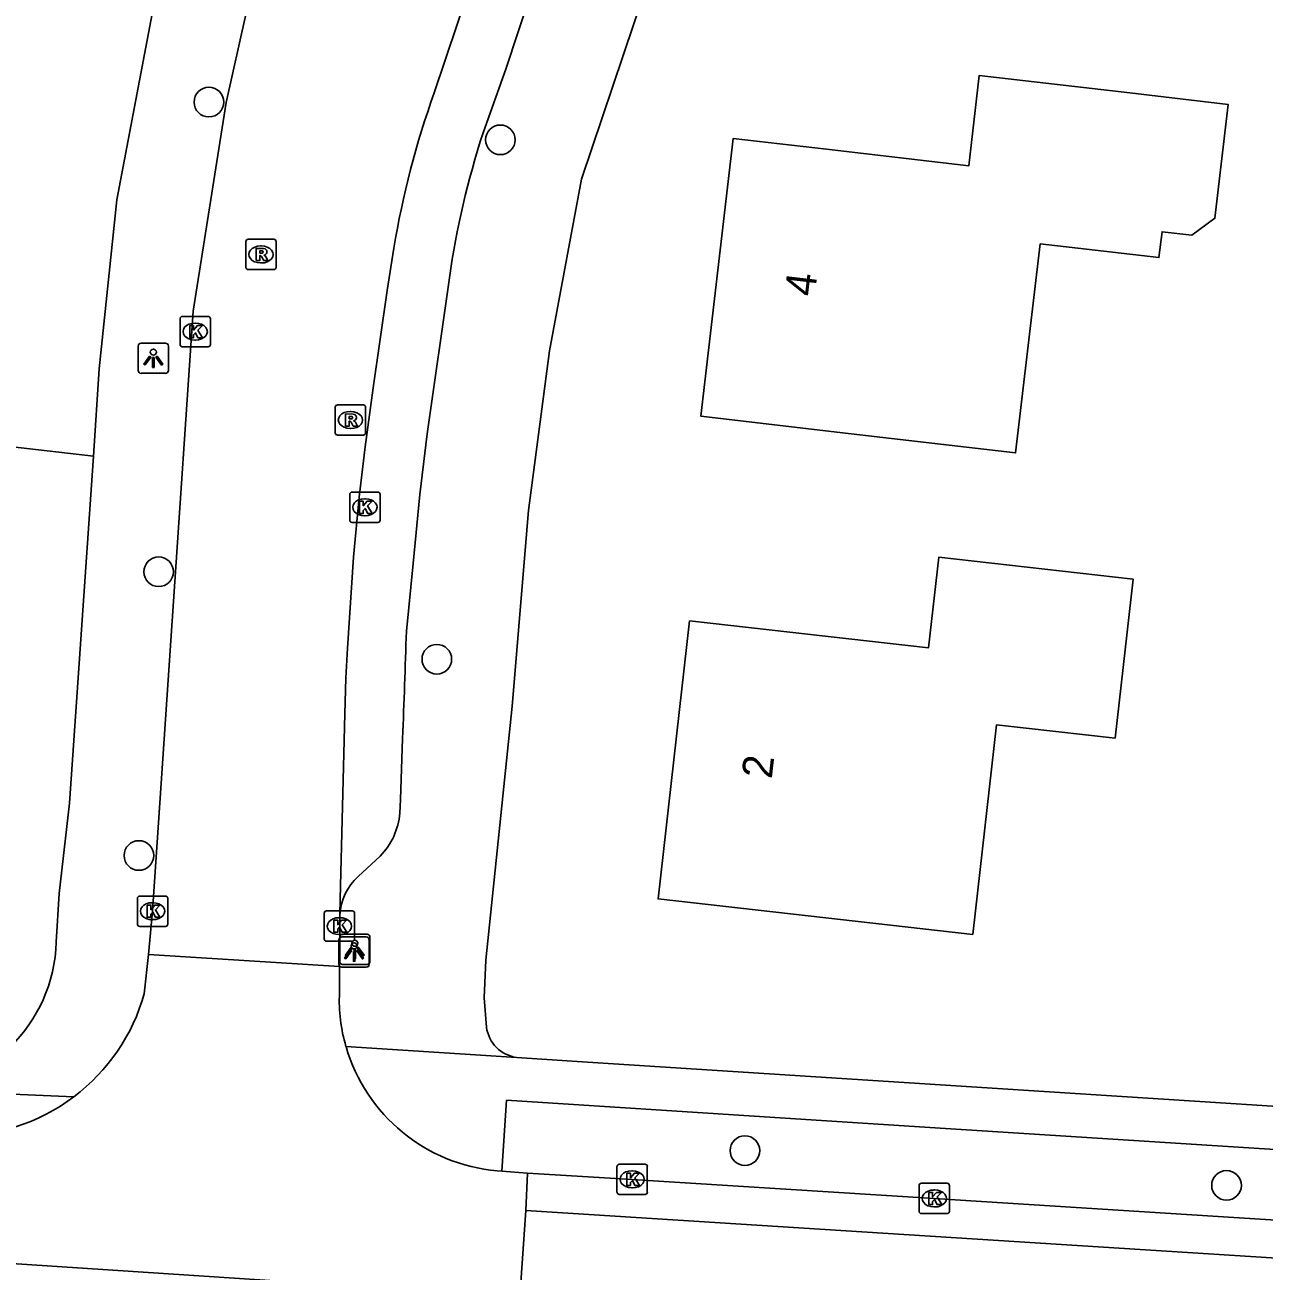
# Model space of a CAD drawing. Extents: x 162398 to 163643, y 386453 to 387397.
# Drawn here: x 162713.09 to 162753.98, y 386597.2 to 386638.31 of the extents above; entities that cross this region are included whole.
import ezdxf

# ---------------------------------------------------------------- set-up
doc = ezdxf.new("R2010")
doc.units = 0
for name, color, linetype in [('IMGEO_Boom', 7, 'Continuous'), ('IMGEO_Groenvoorziening', 7, 'Continuous'), ('IMGEO_Kolk', 7, 'Continuous'), ('IMGEO_Lichtpunt', 7, 'Continuous'), ('IMGEO_Pand', 7, 'Continuous'), ('IMGEO_Pand_nummerreeks', 7, 'Continuous'), ('IMGEO_Rijbaan_lokaal_gesloten', 7, 'Continuous'), ('IMGEO_Rijbaan_lokaal_open', 7, 'Continuous'), ('IMGEO_Rioolput', 7, 'Continuous'), ('IMGEO_Voetpad_open', 7, 'Continuous')]:
    doc.layers.add(name, color=color, linetype=linetype)

msp = doc.modelspace()

# ---------------------------------------------------------------- linework, layer by layer
at = {"layer": 'IMGEO_Boom'}
for centre in [(162719.162, 386635.768), (162728.778, 386634.522), (162717.504, 386620.272), (162726.682, 386617.387), (162716.852, 386610.912), (162736.848, 386601.175), (162752.739, 386600.03)]:
    msp.add_circle(centre, 0.489, dxfattribs=at)
at = {"layer": 'IMGEO_Groenvoorziening'}
msp.add_lwpolyline([(162715.359, 386624.084), (162712.686, 386624.392), (162712.66, 386624.395)], dxfattribs=at)
at = {"layer": 'IMGEO_Kolk'}
for p, q in [((162718.208, 386627.769), (162718.208, 386628.621)), ((162718.283, 386628.695), (162719.135, 386628.695)), ((162718.696, 386628.475), (162718.721, 386628.475)), ((162719.209, 386628.621), (162719.209, 386627.769)), ((162719.135, 386627.695), (162718.283, 386627.695)), ((162718.719, 386627.915), (162718.694, 386627.915)), ((162723.808, 386621.974), (162723.808, 386622.826)), ((162723.883, 386622.9), (162724.735, 386622.9)), ((162724.809, 386622.826), (162724.809, 386621.974)), ((162724.296, 386622.68), (162724.321, 386622.68)), ((162724.735, 386621.9), (162723.883, 386621.9)), ((162724.319, 386622.12), (162724.294, 386622.12)), ((162716.877, 386609.575), (162717.729, 386609.575)), ((162716.802, 386608.649), (162716.802, 386609.501)), ((162717.29, 386609.355), (162717.315, 386609.355)), ((162717.803, 386609.501), (162717.803, 386608.649)), ((162717.313, 386608.795), (162717.288, 386608.795)), ((162722.967, 386608.155), (162722.967, 386609.007)), ((162723.042, 386609.081), (162723.894, 386609.081)), ((162723.455, 386608.861), (162723.48, 386608.861)), ((162723.968, 386609.007), (162723.968, 386608.155)), ((162717.729, 386608.575), (162716.877, 386608.575)), ((162723.894, 386608.081), (162723.042, 386608.081)), ((162723.478, 386608.301), (162723.453, 386608.301)), ((162732.627, 386599.802), (162732.627, 386600.654)), ((162732.702, 386600.728), (162733.554, 386600.728)), ((162733.115, 386600.508), (162733.14, 386600.508)), ((162733.628, 386600.654), (162733.628, 386599.802)), ((162742.671, 386600.097), (162743.523, 386600.097)), ((162733.554, 386599.728), (162732.702, 386599.728)), ((162733.138, 386599.948), (162733.113, 386599.948)), ((162742.596, 386599.171), (162742.596, 386600.023)), ((162743.084, 386599.877), (162743.109, 386599.877)), ((162743.597, 386600.023), (162743.597, 386599.171)), ((162743.107, 386599.317), (162743.082, 386599.317)), ((162743.523, 386599.097), (162742.671, 386599.097))]:
    msp.add_line(p, q, dxfattribs=at)
for points in [[(162718.208, 386627.769), (162718.208, 386628.621)], [(162718.283, 386628.695), (162719.135, 386628.695)], [(162719.209, 386628.621), (162719.209, 386627.769)], [(162718.529, 386628.395), (162718.652, 386628.395), (162718.652, 386628.244), (162718.782, 386628.395), (162718.946, 386628.395), (162718.8, 386628.244), (162718.953, 386627.995), (162718.801, 386627.995), (162718.716, 386628.159), (162718.652, 386628.092), (162718.652, 386627.995), (162718.529, 386627.995), (162718.529, 386628.395)], [(162719.135, 386627.695), (162718.283, 386627.695)], [(162723.808, 386621.974), (162723.808, 386622.826)], [(162723.883, 386622.9), (162724.735, 386622.9)], [(162724.809, 386622.826), (162724.809, 386621.974)], [(162724.129, 386622.6), (162724.252, 386622.6), (162724.252, 386622.449), (162724.382, 386622.6), (162724.546, 386622.6), (162724.4, 386622.449), (162724.553, 386622.2), (162724.401, 386622.2), (162724.316, 386622.364), (162724.252, 386622.297), (162724.252, 386622.2), (162724.129, 386622.2), (162724.129, 386622.6)], [(162724.735, 386621.9), (162723.883, 386621.9)], [(162716.877, 386609.575), (162717.729, 386609.575)], [(162716.802, 386608.649), (162716.802, 386609.501)], [(162717.123, 386609.275), (162717.246, 386609.275), (162717.246, 386609.124), (162717.376, 386609.275), (162717.54, 386609.275), (162717.394, 386609.124), (162717.547, 386608.875), (162717.395, 386608.875), (162717.31, 386609.039), (162717.246, 386608.972), (162717.246, 386608.875), (162717.123, 386608.875), (162717.123, 386609.275)], [(162717.803, 386609.501), (162717.803, 386608.649)], [(162722.967, 386608.155), (162722.967, 386609.007)], [(162723.042, 386609.081), (162723.894, 386609.081)], [(162723.288, 386608.781), (162723.411, 386608.781), (162723.411, 386608.63), (162723.541, 386608.781), (162723.705, 386608.781), (162723.559, 386608.63), (162723.712, 386608.381), (162723.56, 386608.381), (162723.475, 386608.545), (162723.411, 386608.478), (162723.411, 386608.381), (162723.288, 386608.381), (162723.288, 386608.781)], [(162723.968, 386609.007), (162723.968, 386608.155)], [(162717.729, 386608.575), (162716.877, 386608.575)], [(162723.894, 386608.081), (162723.042, 386608.081)], [(162732.627, 386599.802), (162732.627, 386600.654)], [(162732.702, 386600.728), (162733.554, 386600.728)], [(162733.628, 386600.654), (162733.628, 386599.802)], [(162732.948, 386600.428), (162733.071, 386600.428), (162733.071, 386600.277), (162733.201, 386600.428), (162733.365, 386600.428), (162733.219, 386600.277), (162733.372, 386600.028), (162733.22, 386600.028), (162733.135, 386600.192), (162733.071, 386600.125), (162733.071, 386600.028), (162732.948, 386600.028), (162732.948, 386600.428)], [(162742.671, 386600.097), (162743.523, 386600.097)], [(162733.554, 386599.728), (162732.702, 386599.728)], [(162742.596, 386599.171), (162742.596, 386600.023)], [(162742.917, 386599.797), (162743.04, 386599.797), (162743.04, 386599.646), (162743.17, 386599.797), (162743.334, 386599.797), (162743.188, 386599.646), (162743.341, 386599.397), (162743.189, 386599.397), (162743.104, 386599.561), (162743.04, 386599.494), (162743.04, 386599.397), (162742.917, 386599.397), (162742.917, 386599.797)], [(162743.597, 386600.023), (162743.597, 386599.171)], [(162743.523, 386599.097), (162742.671, 386599.097)]]:
    msp.add_lwpolyline(points, dxfattribs=at)
for centre, start, end in [((162718.285, 386628.619), 91.552, 178.448), ((162718.285, 386628.619), 91.552, 178.448), ((162719.133, 386628.619), 1.552, 88.448), ((162719.133, 386628.619), 1.552, 88.448), ((162718.285, 386627.771), 181.552, 268.448), ((162718.285, 386627.771), 181.552, 268.448), ((162719.133, 386627.771), 271.552, 358.448), ((162719.133, 386627.771), 271.552, 358.448), ((162723.885, 386622.824), 91.552, 178.448), ((162723.885, 386622.824), 91.552, 178.448), ((162724.733, 386622.824), 1.552, 88.448), ((162724.733, 386622.824), 1.552, 88.448), ((162723.885, 386621.976), 181.552, 268.448), ((162723.885, 386621.976), 181.552, 268.448), ((162724.733, 386621.976), 271.552, 358.448), ((162724.733, 386621.976), 271.552, 358.448), ((162716.879, 386609.499), 91.552, 178.448), ((162716.879, 386609.499), 91.552, 178.448), ((162717.727, 386609.499), 1.552, 88.448), ((162717.727, 386609.499), 1.552, 88.448), ((162723.044, 386609.005), 91.552, 178.448), ((162723.044, 386609.005), 91.552, 178.448), ((162723.892, 386609.005), 1.552, 88.448), ((162723.892, 386609.005), 1.552, 88.448), ((162716.879, 386608.651), 181.552, 268.448), ((162716.879, 386608.651), 181.552, 268.448), ((162717.727, 386608.651), 271.552, 358.448), ((162717.727, 386608.651), 271.552, 358.448), ((162723.044, 386608.157), 181.552, 268.448), ((162723.044, 386608.157), 181.552, 268.448), ((162723.892, 386608.157), 271.552, 358.448), ((162723.892, 386608.157), 271.552, 358.448), ((162732.704, 386600.652), 91.552, 178.448), ((162732.704, 386600.652), 91.552, 178.448), ((162733.552, 386600.652), 1.552, 88.448), ((162733.552, 386600.652), 1.552, 88.448), ((162742.673, 386600.021), 91.552, 178.448), ((162742.673, 386600.021), 91.552, 178.448), ((162743.521, 386600.021), 1.552, 88.448), ((162743.521, 386600.021), 1.552, 88.448), ((162732.704, 386599.804), 181.552, 268.448), ((162732.704, 386599.804), 181.552, 268.448), ((162733.552, 386599.804), 271.552, 358.448), ((162733.552, 386599.804), 271.552, 358.448), ((162742.673, 386599.173), 181.552, 268.448), ((162742.673, 386599.173), 181.552, 268.448), ((162743.521, 386599.173), 271.552, 358.448), ((162743.521, 386599.173), 271.552, 358.448)]:
    msp.add_arc(centre, 0.0765, start, end, dxfattribs=at)
for centre, major_axis, ratio, start_param, end_param in [((162718.695, 386628.195), (-0.387, 0.002), 0.722429, 4.712389, 7.853982), ((162718.72, 386628.195), (-0.39, 0.002), 0.717154, 1.570796, 4.712389), ((162724.295, 386622.4), (-0.387, 0.002), 0.722429, 4.712389, 7.853982), ((162724.32, 386622.4), (-0.39, 0.002), 0.717154, 1.570796, 4.712389), ((162717.289, 386609.075), (-0.387, 0.002), 0.722429, 4.712389, 7.853982), ((162717.314, 386609.075), (-0.39, 0.002), 0.717154, 1.570796, 4.712389), ((162723.454, 386608.581), (-0.387, 0.002), 0.722429, 4.712389, 7.853982), ((162723.479, 386608.581), (-0.39, 0.002), 0.717154, 1.570796, 4.712389), ((162733.114, 386600.228), (-0.387, 0.002), 0.722429, 4.712389, 7.853982), ((162733.139, 386600.228), (-0.39, 0.002), 0.717154, 1.570796, 4.712389), ((162743.083, 386599.597), (-0.387, 0.002), 0.722429, 4.712389, 7.853982), ((162743.108, 386599.597), (-0.39, 0.002), 0.717154, 1.570796, 4.712389)]:
    msp.add_ellipse(centre, major_axis=major_axis, ratio=ratio, start_param=start_param, end_param=end_param, dxfattribs=at)
at = {"layer": 'IMGEO_Lichtpunt'}
for p, q in [((162716.829, 386627.72), (162716.829, 386626.913)), ((162716.829, 386627.72), (162716.829, 386626.913)), ((162717.731, 386627.815), (162716.923, 386627.815)), ((162717.731, 386627.815), (162716.923, 386627.815)), ((162717.825, 386626.913), (162717.825, 386627.72)), ((162717.825, 386626.913), (162717.825, 386627.72)), ((162716.923, 386626.819), (162717.731, 386626.819)), ((162716.923, 386626.819), (162717.731, 386626.819)), ((162724.379, 386608.314), (162723.571, 386608.314)), ((162724.379, 386608.314), (162723.571, 386608.314)), ((162723.454, 386608.129), (162723.454, 386607.322)), ((162723.454, 386608.129), (162723.454, 386607.322)), ((162723.477, 386608.219), (162723.477, 386607.412)), ((162723.477, 386608.219), (162723.477, 386607.412)), ((162724.356, 386608.224), (162723.548, 386608.224)), ((162724.356, 386608.224), (162723.548, 386608.224)), ((162724.45, 386607.322), (162724.45, 386608.129)), ((162724.45, 386607.322), (162724.45, 386608.129)), ((162724.473, 386607.412), (162724.473, 386608.219)), ((162724.473, 386607.412), (162724.473, 386608.219)), ((162723.548, 386607.228), (162724.356, 386607.228)), ((162723.548, 386607.228), (162724.356, 386607.228)), ((162723.571, 386607.318), (162724.379, 386607.318)), ((162723.571, 386607.318), (162724.379, 386607.318))]:
    msp.add_line(p, q, dxfattribs=at)
for points in [[(162717.203, 386627.384), (162717.242, 386627.356), (162717.054, 386627.094), (162717.016, 386627.121), (162717.203, 386627.384)], [(162717.305, 386627.336), (162717.352, 386627.336), (162717.352, 386627.014), (162717.305, 386627.014), (162717.305, 386627.336)], [(162717.415, 386627.356), (162717.453, 386627.383), (162717.64, 386627.121), (162717.601, 386627.093), (162717.415, 386627.356)], [(162723.828, 386607.793), (162723.867, 386607.765), (162723.679, 386607.503), (162723.641, 386607.53), (162723.828, 386607.793)], [(162723.851, 386607.883), (162723.89, 386607.855), (162723.702, 386607.593), (162723.664, 386607.62), (162723.851, 386607.883)], [(162723.93, 386607.745), (162723.977, 386607.745), (162723.977, 386607.423), (162723.93, 386607.423), (162723.93, 386607.745)], [(162723.953, 386607.835), (162724, 386607.835), (162724, 386607.513), (162723.953, 386607.513), (162723.953, 386607.835)], [(162724.04, 386607.765), (162724.078, 386607.792), (162724.265, 386607.53), (162724.226, 386607.502), (162724.04, 386607.765)], [(162724.063, 386607.855), (162724.101, 386607.882), (162724.288, 386607.62), (162724.249, 386607.592), (162724.063, 386607.855)]]:
    msp.add_lwpolyline(points, dxfattribs=at)
for centre in [(162717.328, 386627.518), (162723.953, 386607.927), (162723.976, 386608.017)]:
    msp.add_circle(centre, 0.0994, dxfattribs=at)
for centre, start, end in [((162716.923, 386627.72), 90, 180), ((162716.923, 386627.72), 90, 180), ((162717.731, 386627.72), 0, 90), ((162717.731, 386627.72), 0, 90), ((162716.923, 386626.913), 180, 270), ((162716.923, 386626.913), 180, 270), ((162717.731, 386626.913), 270, 0), ((162717.731, 386626.913), 270, 360), ((162723.571, 386608.219), 90, 180), ((162723.571, 386608.219), 90, 180), ((162724.379, 386608.219), 0, 90), ((162724.379, 386608.219), 0, 90), ((162723.548, 386608.129), 90, 180), ((162723.548, 386608.129), 90, 180), ((162724.356, 386608.129), 0, 90), ((162724.356, 386608.129), 0, 90), ((162723.548, 386607.322), 180, 270), ((162723.548, 386607.322), 180, 270), ((162723.571, 386607.412), 180, 270), ((162723.571, 386607.412), 180, 270), ((162724.356, 386607.322), 270, 0), ((162724.356, 386607.322), 270, 360), ((162724.379, 386607.412), 270, 0), ((162724.379, 386607.412), 270, 360)]:
    msp.add_arc(centre, 0.0946, start, end, dxfattribs=at)
at = {"layer": 'IMGEO_Pand'}
for points in [[(162746.587, 386631.094), (162745.779, 386624.193), (162740.356, 386624.828), (162735.389, 386625.409), (162736.461, 386634.569), (162739.541, 386634.209), (162744.232, 386633.66), (162744.581, 386636.648), (162749.548, 386636.067), (162751.125, 386635.882), (162752.797, 386635.686), (162752.357, 386631.935), (162751.592, 386631.373), (162750.611, 386631.488), (162750.511, 386630.635), (162746.587, 386631.094)], [(162749.07, 386614.78), (162745.15, 386615.223), (162744.367, 386608.307), (162733.985, 386609.482), (162735.023, 386618.653), (162742.905, 386617.761), (162743.244, 386620.753), (162749.664, 386620.026), (162749.07, 386614.78)]]:
    msp.add_lwpolyline(points, dxfattribs=at)
at = {"layer": 'IMGEO_Rijbaan_lokaal_gesloten'}
for points in [[(162729.676, 386600.429), (162733.128, 386600.228), (162743.097, 386599.597), (162758.54, 386598.613), (162773.98, 386597.628), (162777.205, 386597.414)], [(162777.205, 386597.414), (162777.106, 386596.182), (162742.964, 386598.357), (162729.614, 386599.202)]]:
    msp.add_lwpolyline(points, dxfattribs=at)
at = {"layer": 'IMGEO_Rijbaan_lokaal_open'}
for points in [[(162726.599, 386636.073), (162727.35, 386638.325), (162728.125, 386640.647), (162729.554, 386644.862), (162730.39, 386647.436), (162731.37, 386650.353), (162732.546, 386653.782), (162733.829, 386657.575), (162736.244, 386664.738), (162736.362, 386665.025)], [(162717.165, 386607.646), (162717.303, 386609.075), (162718.642, 386628.868), (162719.73, 386635.752), (162720.379, 386638.661), (162722.597, 386645.776), (162728.857, 386664.611)], [(162723.485, 386608.949), (162723.496, 386609.469), (162723.644, 386615.584), (162723.678, 386616.758), (162723.732, 386617.753), (162723.938, 386620.755), (162724.125, 386622.738), (162724.316, 386624.392), (162724.577, 386626.336), (162725.041, 386629.554), (162725.266, 386630.952)], [(162723.476, 386607.248), (162723.485, 386608.949)], [(162717.03, 386606.349), (162717.165, 386607.646)], [(162717.165, 386607.646), (162723.476, 386607.248)], [(162723.476, 386607.248), (162723.471, 386606.381)], [(162728.827, 386600.5), (162728.672, 386600.508)], [(162729.676, 386600.429), (162728.827, 386600.5)], [(162729.614, 386599.202), (162729.676, 386600.429)], [(162729.422, 386596.356), (162729.614, 386599.202)], [(162710.397, 386596.361), (162710.468, 386597.592), (162728.355, 386596.42), (162728.298, 386595.17)]]:
    msp.add_lwpolyline(points, dxfattribs=at)
for centre, radius, start, end in [((162753.634, 386626.302), 28.746, 160.1286, 170.6907), ((162710.819, 386608.108), 6.455, 307.0345, 344.1867), ((162728.789, 386606.125), 5.325, 177.2466, 196.5334), ((162729.177, 386606.204), 5.718, 196.1853, 264.9374), ((162710.818, 386608.116), 6.463, 268.8756, 306.9985)]:
    msp.add_arc(centre, radius, start, end, dxfattribs=at)
at = {"layer": 'IMGEO_Rioolput'}
for p, q in [((162720.379, 386630.314), (162720.379, 386631.166)), ((162720.454, 386631.24), (162721.306, 386631.24)), ((162720.867, 386631.02), (162720.892, 386631.02)), ((162721.38, 386631.166), (162721.38, 386630.314)), ((162721.306, 386630.24), (162720.454, 386630.24)), ((162720.89, 386630.46), (162720.865, 386630.46)), ((162723.332, 386624.853), (162723.332, 386625.705)), ((162723.407, 386625.779), (162724.259, 386625.779)), ((162724.333, 386625.705), (162724.333, 386624.853)), ((162723.82, 386625.559), (162723.845, 386625.559)), ((162724.259, 386624.779), (162723.407, 386624.779)), ((162723.843, 386624.999), (162723.818, 386624.999))]:
    msp.add_line(p, q, dxfattribs=at)
for points in [[(162720.379, 386630.314), (162720.379, 386631.166)], [(162720.454, 386631.24), (162721.306, 386631.24)], [(162720.968, 386630.938), (162720.716, 386630.94), (162720.716, 386630.54)], [(162721.38, 386631.166), (162721.38, 386630.314)], [(162720.716, 386630.54), (162720.84, 386630.54), (162720.84, 386630.702), (162720.851, 386630.702)], [(162720.894, 386630.859), (162720.84, 386630.859), (162720.84, 386630.778)], [(162720.84, 386630.778), (162720.892, 386630.778)], [(162720.898, 386630.673), (162720.969, 386630.54), (162721.109, 386630.54), (162721.044, 386630.666)], [(162721.306, 386630.24), (162720.454, 386630.24)], [(162723.332, 386624.853), (162723.332, 386625.705)], [(162723.407, 386625.779), (162724.259, 386625.779)], [(162724.333, 386625.705), (162724.333, 386624.853)], [(162723.921, 386625.477), (162723.669, 386625.479), (162723.669, 386625.079)], [(162723.669, 386625.079), (162723.793, 386625.079), (162723.793, 386625.241), (162723.804, 386625.241)], [(162723.847, 386625.398), (162723.793, 386625.398), (162723.793, 386625.317)], [(162723.793, 386625.317), (162723.845, 386625.317)], [(162723.851, 386625.212), (162723.922, 386625.079), (162724.062, 386625.079), (162723.997, 386625.205)], [(162724.259, 386624.779), (162723.407, 386624.779)]]:
    msp.add_lwpolyline(points, dxfattribs=at)
for centre, radius, start, end in [((162720.456, 386631.164), 0.0765, 91.552, 178.448), ((162720.456, 386631.164), 0.0765, 91.552, 178.448), ((162720.967, 386630.828), 0.109, 350.3612, 89.416), ((162721.304, 386631.164), 0.0765, 1.552, 88.448), ((162721.304, 386631.164), 0.0765, 1.552, 88.448), ((162720.85, 386630.649), 0.0533, 26.0293, 88.6989), ((162720.876, 386630.967), 0.19, 274.7715, 282.9687), ((162720.9, 386630.763), 0.0964, 77.0061, 93.1865), ((162720.914, 386630.82), 0.0378, 276.6634, 79.6772), ((162720.965, 386630.828), 0.112, 277.5842, 350.9817), ((162720.949, 386630.613), 0.108, 29.5134, 73.7905), ((162720.456, 386630.316), 0.0765, 181.552, 268.448), ((162720.456, 386630.316), 0.0765, 181.552, 268.448), ((162721.304, 386630.316), 0.0765, 271.552, 358.448), ((162721.304, 386630.316), 0.0765, 271.552, 358.448), ((162723.409, 386625.703), 0.0765, 91.552, 178.448), ((162723.409, 386625.703), 0.0765, 91.552, 178.448), ((162724.257, 386625.703), 0.0765, 1.552, 88.448), ((162724.257, 386625.703), 0.0765, 1.552, 88.448), ((162723.803, 386625.188), 0.0533, 26.0293, 88.6989), ((162723.829, 386625.506), 0.19, 274.7715, 282.9687), ((162723.853, 386625.302), 0.0964, 77.0061, 93.1865), ((162723.867, 386625.359), 0.0378, 276.6634, 79.6772), ((162723.92, 386625.367), 0.109, 350.3612, 89.416), ((162723.918, 386625.367), 0.112, 277.5842, 350.9817), ((162723.902, 386625.152), 0.108, 29.5134, 73.7905), ((162723.409, 386624.855), 0.0765, 181.552, 268.448), ((162723.409, 386624.855), 0.0765, 181.552, 268.448), ((162724.257, 386624.855), 0.0765, 271.552, 358.448), ((162724.257, 386624.855), 0.0765, 271.552, 358.448)]:
    msp.add_arc(centre, radius, start, end, dxfattribs=at)
for centre, major_axis, ratio, start_param, end_param in [((162720.866, 386630.74), (-0.387, 0.002), 0.722429, 4.712389, 7.853982), ((162720.891, 386630.74), (-0.39, 0.002), 0.717154, 1.570796, 4.712389), ((162723.819, 386625.279), (-0.387, 0.002), 0.722429, 4.712389, 7.853982), ((162723.844, 386625.279), (-0.39, 0.002), 0.717154, 1.570796, 4.712389)]:
    msp.add_ellipse(centre, major_axis=major_axis, ratio=ratio, start_param=start_param, end_param=end_param, dxfattribs=at)
at = {"layer": 'IMGEO_Voetpad_open'}
for points in [[(162728.319, 386605.252), (162728.244, 386606.221), (162728.3, 386607.457), (162729.171, 386615.834), (162729.703, 386622.29), (162730.396, 386627.558), (162731.458, 386633.225), (162743.548, 386669.105)], [(162725.964, 386665.516), (162718.999, 386644.672), (162717.288, 386638.674), (162716.12, 386632.546), (162715.541, 386626.964), (162715.359, 386624.084)], [(162728.212, 386634.757), (162728.966, 386636.886), (162730.13, 386640.396), (162732.073, 386646.155), (162733.528, 386650.457), (162735.933, 386657.606), (162737.317, 386661.713)], [(162725.677, 386618.312), (162725.902, 386620.54), (162726.118, 386622.826), (162726.36, 386624.827), (162727.098, 386629.974)], [(162715.359, 386624.084), (162714.566, 386612.643), (162714.22, 386609.663), (162714.124, 386608.058)], [(162725.464, 386612.307), (162725.487, 386612.759), (162725.55, 386614.776)], [(162724.083, 386610.223), (162724.81, 386610.892)], [(162723.685, 386604.61), (162729.324, 386604.246)], [(162778.233, 386601.111), (162775.14, 386601.306), (162731.31, 386604.112), (162729.324, 386604.246)], [(162714.707, 386602.955), (162709.121, 386603.197)], [(162728.827, 386600.5), (162728.986, 386602.84), (162742.954, 386601.941), (162777.289, 386599.753), (162777.205, 386597.414)]]:
    msp.add_lwpolyline(points, dxfattribs=at)
for centre, radius, start, end in [((162754.51, 386626.111), 27.683, 161.8001, 171.978), ((162487.49, 386625.096), 238.283, 357.51763, 358.36843), ((162723.142, 386612.522), 2.332, 315.6696, 354.7185), ((162725.372, 386608.84), 1.89, 133.0024, 176.708), ((162709.132, 386608.191), 4.994, 269.877, 358.4735), ((162729.483, 386605.41), 1.175, 187.7411, 262.2019)]:
    msp.add_arc(centre, radius, start, end, dxfattribs=at)

# ---------------------------------------------------------------- texts
at = {"layer": 'IMGEO_Pand_nummerreeks'}
for s, rotation, p in [('4', 83.3253, (162739.151, 386629.335)), ('2', 83.5426, (162737.733, 386613.422))]:
    msp.add_text(s, height=1, rotation=rotation, dxfattribs=at).set_placement(p)

doc.saveas('drawing.dxf')
